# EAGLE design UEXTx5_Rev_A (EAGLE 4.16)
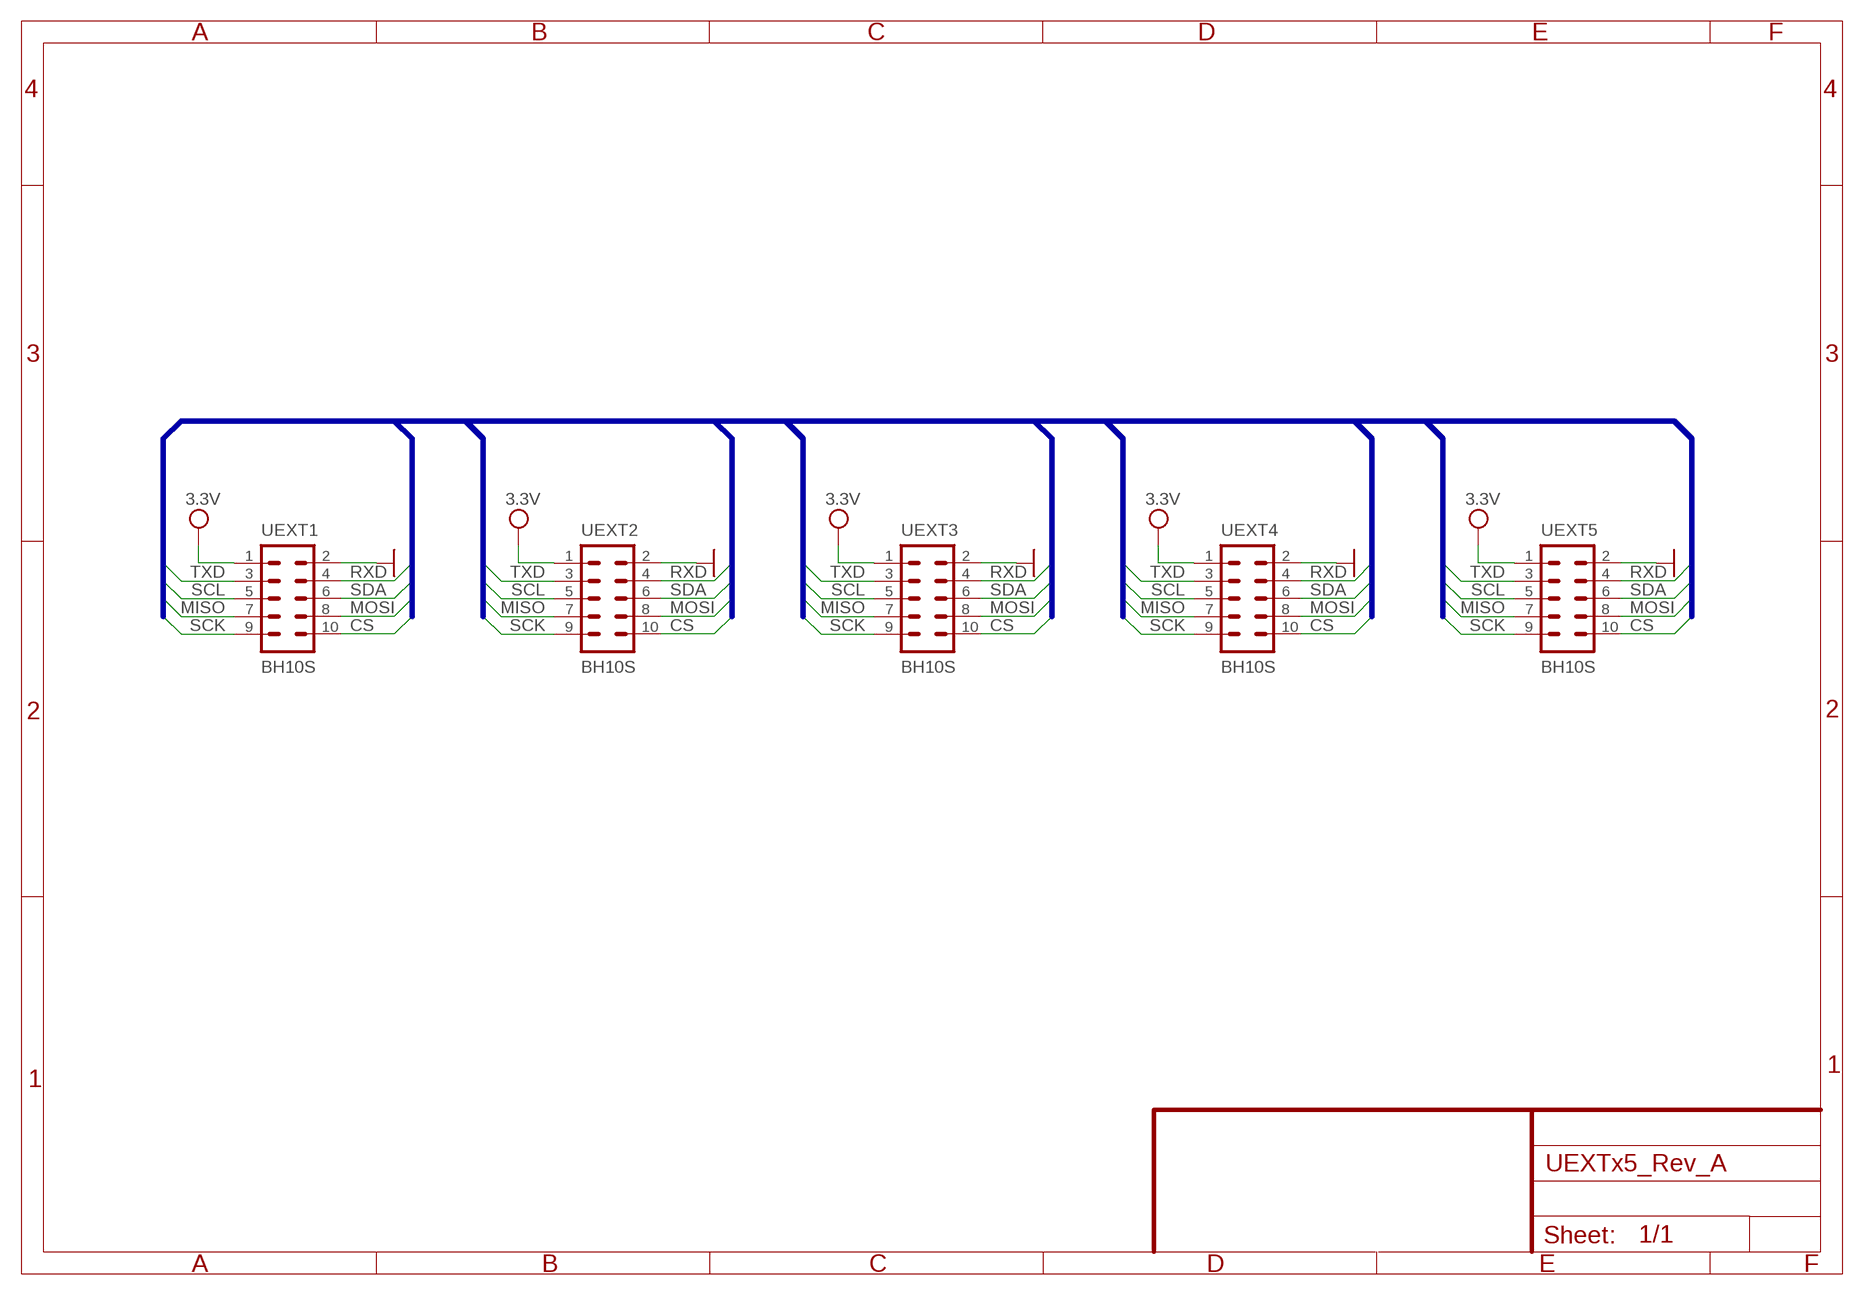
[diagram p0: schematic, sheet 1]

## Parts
UEXT1  BH10S  ML10  [ML10-MALE]
UEXT2  BH10S  ML10  [ML10-MALE]
UEXT3  BH10S  ML10  [ML10-MALE]
UEXT4  BH10S  ML10  [ML10-MALE]
UEXT5  BH10S  ML10  [ML10-MALE]

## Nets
CS: UEXT1.10 UEXT2.10 UEXT3.10 UEXT4.10 UEXT5.10
GND: UEXT1.2 UEXT2.2 UEXT3.2 UEXT4.2 UEXT5.2
MISO: UEXT1.7 UEXT2.7 UEXT3.7 UEXT4.7 UEXT5.7
MOSI: UEXT1.8 UEXT2.8 UEXT3.8 UEXT4.8 UEXT5.8
RXD: UEXT1.4 UEXT2.4 UEXT3.4 UEXT4.4 UEXT5.4
SCK: UEXT1.9 UEXT2.9 UEXT3.9 UEXT4.9 UEXT5.9
SCL: UEXT1.5 UEXT2.5 UEXT3.5 UEXT4.5 UEXT5.5
SDA: UEXT1.6 UEXT2.6 UEXT3.6 UEXT4.6 UEXT5.6
TXD: UEXT1.3 UEXT2.3 UEXT3.3 UEXT4.3 UEXT5.3
VCC: UEXT1.1 UEXT2.1 UEXT3.1 UEXT4.1 UEXT5.1 ; supply symbol labelled 3.3V

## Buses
TXD,RXD,SCL,SDA,MISO,MOSI,SCK,CS

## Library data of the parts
UEXT1-UEXT5 = con-harting-ml:ML10: HARTING

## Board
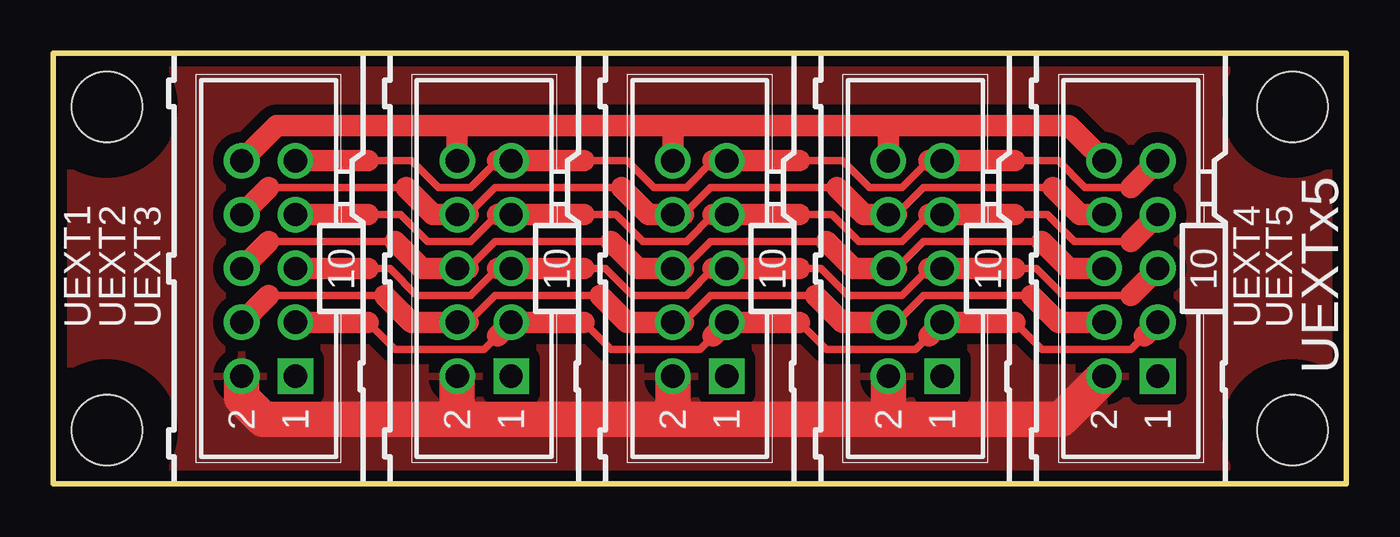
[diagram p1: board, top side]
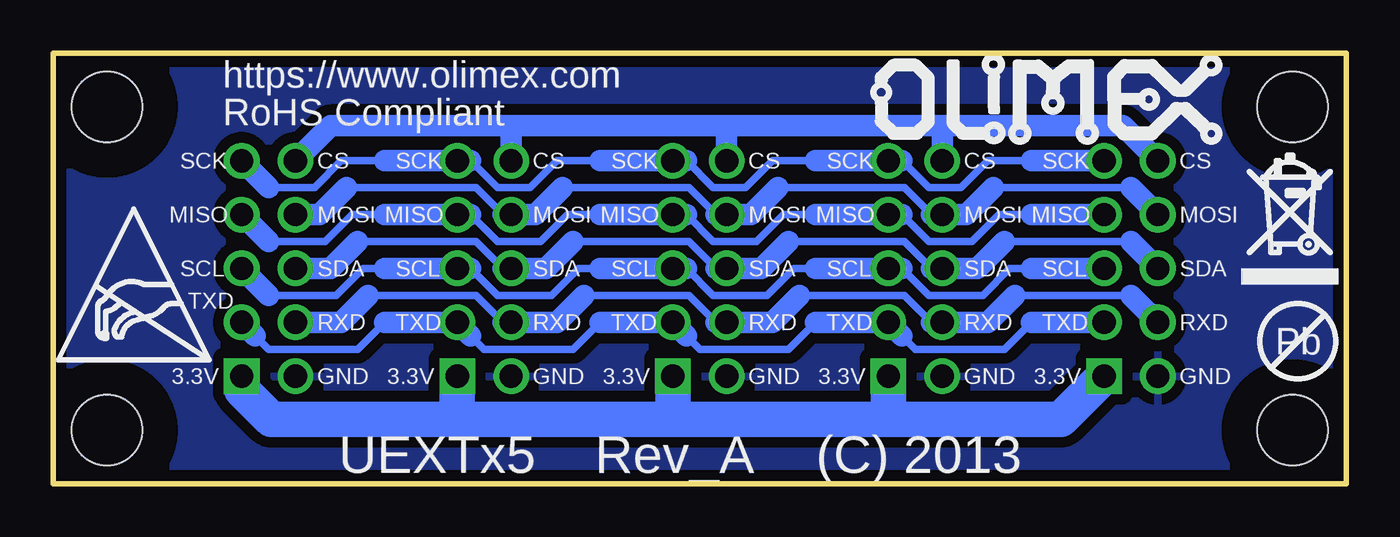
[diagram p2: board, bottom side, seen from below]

Size 60.96 x 20.32 mm. Coordinates in mm from the lower left corner, seen from the top.
Outline: 0,0 60.96,0 60.96,20.32 0,20.32 0,0
Copper layers (1+16): Top 0.035mm / dielectric 1.5mm / Bottom 0.035mm
Design rules "default": minimum track width 10mil, minimum drill 24mil, track to track 10mil, track to pad 10mil, pad to pad 10mil, via to via 10mil, smd to smd 10mil, copper to edge 10mil, drill to drill 8mil, minimum pad ring 10mil, minimum via ring 8mil, stop-mask expansion 4mil, vias tented up to drill 25mil, thermal gap 20mil
Holes 3.3 mm at 58.42,17.78 2.54,17.78 2.54,2.54 58.42,2.54
tRestrict: area -0.2,15.1 to 5.2,20.5; area -0.2,-0.2 to 5.2,5.2; area 55.7,-0.2 to 61.1,5.2; area 55.7,15.1 to 61.1,20.5
bRestrict: area -0.2,15.1 to 5.2,20.5; area -0.2,-0.2 to 5.2,5.2; area 55.7,-0.2 to 61.1,5.2; area 55.7,15.1 to 61.1,20.5

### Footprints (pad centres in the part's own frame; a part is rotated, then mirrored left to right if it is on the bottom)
ML10-MALE = drill 1.1 pad 1.676 square: 1 -5.08,-1.27 | drill 1.1 pad 1.676 round: 2 -5.08,1.27; 3 -2.54,-1.27; 4 -2.54,1.27; 5 0,-1.27; 6 0,1.27; 7 2.54,-1.27; 8 2.54,1.27; 9 5.08,-1.27; 10 5.08,1.27

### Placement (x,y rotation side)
U$1  [PB_SMALL]  2.29,6.73 0 bottom
U$2  [RECYCLE_BIN1/8]  4.95,9.4 0 bottom
U$4  [ESD_SYMBOL]  60.71,5.84 0 bottom
U$5  [OLIMEX1_V]  4.7,15.88 0 bottom
UEXT1  10.16,10.16 90 top
UEXT2  20.32,10.16 90 top
UEXT3  30.48,10.16 90 top
UEXT4  40.64,10.16 90 top
UEXT5  50.8,10.16 90 top

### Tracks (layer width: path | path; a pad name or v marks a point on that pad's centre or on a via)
CS
  Top 1.016: UEXT1.10 10.54,16.89 19.05,16.89 | 19.05,16.89 29.21,16.89 | 29.21,16.89 39.37,16.89 | 39.37,16.89 47.88,16.89 UEXT5.10 | 39.37,16.89 UEXT4.10 | 29.21,16.89 UEXT3.10 | 19.05,16.89 UEXT2.10
  Bottom 1.016: UEXT1.10 10.54,16.89 19.05,16.89 | 19.05,16.89 UEXT2.10 | 19.05,16.89 29.21,16.89 | 29.21,16.89 UEXT3.10 | 29.21,16.89 39.37,16.89 | 39.37,16.89 UEXT4.10 | 39.37,16.89 47.88,16.89 UEXT5.10
GND
  Top 1.676: UEXT5.2 47.5,3.05 39.37,3.05 | UEXT1.2 8.89,4.06 9.91,3.05 19.05,3.05 | 19.05,3.05 29.21,3.05 | 29.21,3.05 39.37,3.05 | 19.05,3.05 UEXT2.2 | 29.21,3.05 UEXT3.2 | 39.37,3.05 UEXT4.2
  pour Bottom (isolate 0.508): -7.62,22.86 -7.62,-2.54 71.12,-2.54 71.12,22.86
  pour Top (isolate 0.508): -7.62,22.86 -7.62,-2.54 66.04,-2.54 66.04,22.86
MISO
  Top 0.356: 14.86,12.7 16.38,12.7 17.65,11.43 19.68,11.43 20.95,12.7 | 25.02,12.7 26.54,12.7 27.81,11.43 29.84,11.43 31.11,12.7 | 35.18,12.7 36.7,12.7 37.97,11.43 40.01,11.43 41.27,12.7 | 45.34,12.7 46.86,12.7 48.13,11.43 50.8,11.43
  Top 1.016: UEXT1.7 14.86,12.7 | 20.95,12.7 UEXT2.7 25.02,12.7 | 31.11,12.7 UEXT3.7 35.18,12.7 | 41.27,12.7 UEXT4.7 45.34,12.7 | 50.8,11.43 UEXT5.7
  Bottom 0.356: 14.86,12.7 16.38,12.7 17.65,11.43 19.68,11.43 20.95,12.7 | 25.02,12.7 26.54,12.7 27.81,11.43 29.84,11.43 31.11,12.7 | 35.18,12.7 36.7,12.7 37.97,11.43 40.01,11.43 41.27,12.7 | 45.34,12.7 46.86,12.7 48.13,11.43 50.8,11.43
  Bottom 1.016: UEXT1.7 14.86,12.7 | 20.95,12.7 UEXT2.7 25.02,12.7 | 31.11,12.7 UEXT3.7 35.18,12.7 | 41.27,12.7 UEXT4.7 45.34,12.7 | 50.8,11.43 UEXT5.7
MOSI
  Top 0.356: 10.16,13.97 16.64,13.97 | 19.56,12.7 20.83,13.97 26.8,13.97 | 29.72,12.7 30.99,13.97 36.96,13.97 | 39.75,12.7 41.02,13.97 47.12,13.97
  Top 1.016: UEXT1.8 10.16,13.97 | 16.64,13.97 17.91,12.7 UEXT2.8 19.56,12.7 | 26.8,13.97 28.07,12.7 UEXT3.8 29.72,12.7 | 36.96,13.97 38.23,12.7 UEXT4.8 39.75,12.7 | UEXT5.8 48.39,12.7 47.12,13.97
  Bottom 0.356: 10.16,13.97 16.64,13.97 | 19.56,12.7 20.83,13.97 26.8,13.97 | 29.72,12.7 30.99,13.97 36.96,13.97 | 39.75,12.7 41.02,13.97 47.12,13.97
  Bottom 1.016: UEXT1.8 10.16,13.97 | 16.64,13.97 17.91,12.7 UEXT2.8 19.56,12.7 | 26.8,13.97 28.07,12.7 UEXT3.8 29.72,12.7 | 36.96,13.97 38.23,12.7 UEXT4.8 39.75,12.7 | 47.12,13.97 48.39,12.7 UEXT5.8
RXD
  Top 0.356: 10.16,8.89 15.62,8.89 | 19.56,7.62 20.83,8.89 25.78,8.89 | 29.72,7.62 30.99,8.89 35.94,8.89 | 39.75,7.62 41.02,8.89 46.1,8.89
  Top 1.016: UEXT1.4 10.16,8.89 | 15.62,8.89 16.89,7.62 UEXT2.4 19.56,7.62 | 25.78,8.89 27.05,7.62 UEXT3.4 29.72,7.62 | 35.94,8.89 37.21,7.62 UEXT4.4 39.75,7.62 | UEXT5.4 47.37,7.62 46.1,8.89
  Bottom 0.356: 10.16,8.89 15.62,8.89 | 19.56,7.62 20.83,8.89 25.78,8.89 | 29.72,7.62 30.99,8.89 35.94,8.89 | 39.75,7.62 41.02,8.89 46.1,8.89
  Bottom 1.016: UEXT1.4 10.16,8.89 | 15.62,8.89 16.89,7.62 UEXT2.4 19.56,7.62 | 25.78,8.89 27.05,7.62 UEXT3.4 29.72,7.62 | 35.94,8.89 37.21,7.62 UEXT4.4 39.75,7.62 | 46.1,8.89 47.37,7.62 UEXT5.4
SCK
  Top 0.356: 14.86,15.24 16.89,15.24 18.16,13.97 19.68,13.97 20.95,15.24 | 25.02,15.24 27.05,15.24 28.32,13.97 29.84,13.97 31.11,15.24 | 35.18,15.24 37.21,15.24 38.48,13.97 40.01,13.97 41.27,15.24 | 45.34,15.24 47.37,15.24 48.64,13.97 50.8,13.97
  Top 1.016: UEXT1.9 14.86,15.24 | 20.95,15.24 UEXT2.9 25.02,15.24 | 31.11,15.24 UEXT3.9 35.18,15.24 | 41.27,15.24 UEXT4.9 45.34,15.24 | 50.8,13.97 UEXT5.9
  Bottom 0.356: 14.86,15.24 16.89,15.24 18.16,13.97 19.68,13.97 20.95,15.24 | 25.02,15.24 27.05,15.24 28.32,13.97 29.84,13.97 31.11,15.24 | 35.18,15.24 37.21,15.24 38.48,13.97 40.01,13.97 41.27,15.24 | 45.34,15.24 47.37,15.24 48.64,13.97 50.8,13.97
  Bottom 1.016: UEXT1.9 14.86,15.24 | 20.95,15.24 UEXT2.9 25.02,15.24 | 31.11,15.24 UEXT3.9 35.18,15.24 | 41.27,15.24 UEXT4.9 45.34,15.24 | 50.8,13.97 UEXT5.9
SCL
  Top 0.356: 14.86,10.16 15.88,10.16 17.14,8.89 19.68,8.89 20.95,10.16 | 25.02,10.16 26.04,10.16 27.3,8.89 29.84,8.89 31.11,10.16 | 35.18,10.16 36.2,10.16 37.47,8.89 40.01,8.89 41.27,10.16 | 45.34,10.16 46.35,10.16 47.62,8.89 50.8,8.89
  Top 1.016: UEXT1.5 14.86,10.16 | 20.95,10.16 UEXT2.5 25.02,10.16 | 31.11,10.16 UEXT3.5 35.18,10.16 | 41.27,10.16 UEXT4.5 45.34,10.16 | 50.8,8.89 UEXT5.5
  Bottom 0.356: 14.86,10.16 15.88,10.16 17.14,8.89 19.68,8.89 20.95,10.16 | 25.02,10.16 26.04,10.16 27.3,8.89 29.84,8.89 31.11,10.16 | 35.18,10.16 36.2,10.16 37.47,8.89 40.01,8.89 41.27,10.16 | 45.34,10.16 46.35,10.16 47.62,8.89 50.8,8.89
  Bottom 1.016: UEXT1.5 14.86,10.16 | 20.95,10.16 UEXT2.5 25.02,10.16 | 31.11,10.16 UEXT3.5 35.18,10.16 | 41.27,10.16 UEXT4.5 45.34,10.16 | 50.8,8.89 UEXT5.5
SDA
  Top 0.356: 10.16,11.43 16.13,11.43 | 19.56,10.16 20.83,11.43 26.29,11.43 | 29.72,10.16 30.99,11.43 36.45,11.43 | 39.75,10.16 41.02,11.43 46.61,11.43
  Top 1.016: UEXT1.6 10.16,11.43 | 16.13,11.43 17.4,10.16 UEXT2.6 19.56,10.16 | 26.29,11.43 27.56,10.16 UEXT3.6 29.72,10.16 | 36.45,11.43 37.72,10.16 UEXT4.6 39.75,10.16 | UEXT5.6 47.88,10.16 46.61,11.43
  Bottom 0.356: 10.16,11.43 16.13,11.43 | 19.56,10.16 20.83,11.43 26.29,11.43 | 29.72,10.16 30.99,11.43 36.45,11.43 | 39.75,10.16 41.02,11.43 46.61,11.43
  Bottom 1.016: UEXT1.6 10.16,11.43 | 16.13,11.43 17.4,10.16 UEXT2.6 19.56,10.16 | 26.29,11.43 27.56,10.16 UEXT3.6 29.72,10.16 | 36.45,11.43 37.72,10.16 UEXT4.6 39.75,10.16 | 46.61,11.43 47.88,10.16 UEXT5.6
TXD
  Top 0.356: 14.86,7.62 16.13,6.35 20.32,6.35 20.95,6.99 | 25.02,7.62 26.29,6.35 30.48,6.35 31.11,6.99 | 35.18,7.62 36.45,6.35 40.64,6.35 41.27,6.99 | 45.34,7.62 46.61,6.35 50.8,6.35 51.44,6.99
  Top 1.016: UEXT1.3 14.86,7.62 | 20.95,6.99 UEXT2.3 25.02,7.62 | 31.11,6.99 UEXT3.3 35.18,7.62 | 41.27,6.99 UEXT4.3 45.34,7.62 | 51.44,6.99 UEXT5.3
  Bottom 0.356: 14.86,7.62 16.13,6.35 20.32,6.35 20.95,6.99 | 25.02,7.62 26.29,6.35 30.48,6.35 31.11,6.99 | 35.18,7.62 36.45,6.35 40.64,6.35 41.27,6.99 | 45.34,7.62 46.61,6.35 50.8,6.35 51.44,6.99
  Bottom 1.016: UEXT1.3 14.86,7.62 | 20.95,6.99 UEXT2.3 25.02,7.62 | 31.11,6.99 UEXT3.3 35.18,7.62 | 41.27,6.99 UEXT4.3 45.34,7.62 | 51.44,6.99 UEXT5.3
VCC
  Bottom 1.676: UEXT1.1 13.46,3.05 21.59,3.05 | UEXT5.1 52.07,4.45 50.67,3.05 41.91,3.05 | 21.59,3.05 31.75,3.05 | 31.75,3.05 41.91,3.05 | 21.59,3.05 UEXT2.1 | 31.75,3.05 UEXT3.1 | 41.91,3.05 UEXT4.1

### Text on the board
tNames: UEXTx5
bNames: https://www.olimex.com | RoHS Compliant | CS | SCK | CS | SCK | CS | SCK | CS | SCK | CS | SCK | MOSI | MISO | MOSI | MISO | MOSI | MISO | MOSI | MISO | MOSI | MISO | SDA | SCL | SDA | SCL | SDA | SCL | SDA | SCL | SDA | SCL | TXD | RXD | TXD | RXD | TXD | RXD | TXD | RXD | TXD | RXD | GND | 3.3V | GND | 3.3V | GND | 3.3V | GND | 3.3V | GND | 3.3V | (C) 2013 | Rev_A | UEXTx5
